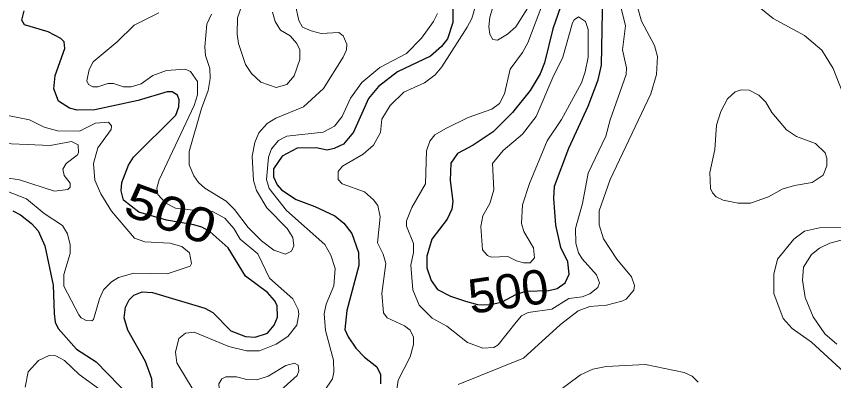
# Model space of a CAD drawing. Extents: x 577 to 602.9, y 7483.8 to 7511.6.
# Drawn here: x 579.985 to 581.887, y 7499.874 to 7500.722 of the extents above; entities that cross this region are included whole.
import ezdxf
from ezdxf.enums import TextEntityAlignment as Align

# ---------------------------------------------------------------- set-up
doc = ezdxf.new("R2010")
doc.units = 0
doc.header["$LTSCALE"] = 0.032
doc.layers.add('1', color=7, linetype='Continuous', lineweight=25)
doc.layers.add('2', color=7, linetype='Continuous', lineweight=13)
doc.layers.add('61', color=7, linetype='Continuous')

msp = doc.modelspace()

# ---------------------------------------------------------------- linework, layer by layer
at = {"layer": '1'}
for points in [[(581.0008, 7500.7727), (581.0008, 7500.7075), (580.9881, 7500.6701), (580.9745, 7500.6518), (580.9483, 7500.6296), (580.872, 7500.593), (580.8274, 7500.5588), (580.8044, 7500.531), (580.7694, 7500.4522), (580.7463, 7500.4244), (580.7241, 7500.4141), (580.7082, 7500.4109), (580.6827, 7500.4157), (580.6382, 7500.4149), (580.6032, 7500.3966), (580.5829, 7500.3672), (580.5829, 7500.3484), (580.5913, 7500.3298), (580.6016, 7500.3178), (580.6358, 7500.2956), (580.6795, 7500.2797), (580.7257, 7500.2574), (580.7471, 7500.2407), (580.7654, 7500.2161), (580.7813, 7500.1723), (580.7821, 7500.1421), (580.7535, 7500.0371)], [(581.2568, 7500.7608), (581.233, 7500.6932), (581.2139, 7500.6136), (581.2036, 7500.5882), (581.1805, 7500.5492), (581.1391, 7500.4983), (581.0946, 7500.453), (581.0477, 7500.422), (581.0111, 7500.4029), (580.996, 7500.3799), (580.9944, 7500.3401), (581.0008, 7500.2908), (580.9984, 7500.2733), (580.9873, 7500.2495), (580.9515, 7500.2033), (580.9404, 7500.1636), (580.9404, 7500.1365), (580.9499, 7500.1071), (580.965, 7500.0864), (580.9952, 7500.0705), (581.0298, 7500.0587), (581.0579, 7500.0508), (581.087, 7500.0502), (581.1154, 7500.057), (581.1469, 7500.0742), (581.1702, 7500.0823), (581.2242, 7500.0833), (581.2433, 7500.088), (581.2624, 7500.1016), (581.2711, 7500.1214), (581.268, 7500.1501), (581.2521, 7500.1835), (581.2401, 7500.2359), (581.2354, 7500.298), (581.237, 7500.3266), (581.2704, 7500.4149), (581.3157, 7500.5127), (581.3387, 7500.5747), (581.3467, 7500.6081), (581.3499, 7500.7743)], [(580.3018, 7500.0793), (580.4235, 7500.0427), (580.4418, 7500.0324), (580.4839, 7499.9894), (580.5181, 7499.9767), (580.5404, 7499.9751), (580.569, 7499.9847), (580.5849, 7500.003), (580.5921, 7500.0212), (580.5913, 7500.0491), (580.5857, 7500.0602), (580.569, 7500.0793), (580.5181, 7500.1167), (580.4776, 7500.1827), (580.4354, 7500.22), (580.4163, 7500.2312), (580.398, 7500.2367), (580.3341, 7500.2477), (580.2699, 7500.2658), (580.2342, 7500.294), (580.2287, 7500.3155), (580.2303, 7500.3353), (580.2454, 7500.3759), (580.2573, 7500.3942), (580.3559, 7500.492), (580.3631, 7500.5111), (580.3639, 7500.5278), (580.3599, 7500.5389), (580.3472, 7500.5461), (580.336, 7500.5461), (580.2684, 7500.5262), (580.1674, 7500.5047), (580.1261, 7500.5039), (580.1086, 7500.5087), (580.0824, 7500.5246), (580.072, 7500.5532), (580.0752, 7500.5842), (580.0975, 7500.647), (580.0959, 7500.6629), (580.0879, 7500.6709), (580.0585, 7500.686), (580.0036, 7500.7027), (579.9973, 7500.713), (580.0028, 7500.7353)], [(579.9766, 7500.2693), (579.9941, 7500.2598), (580.0195, 7500.2399), (580.0354, 7500.2224), (580.0506, 7500.1874), (580.0704, 7500.096), (580.0728, 7500.03), (580.0752, 7500.0101), (580.0816, 7499.995), (580.1245, 7499.9473), (580.1706, 7499.9179), (580.2509, 7499.8344)], [(580.3026, 7499.8399), (580.3002, 7499.8781), (580.2851, 7499.9187), (580.2438, 7499.991), (580.2358, 7500.0197), (580.239, 7500.0451), (580.247, 7500.0618), (580.2581, 7500.0729), (580.2772, 7500.0809), (580.3018, 7500.0793)], [(580.7535, 7500.0371), (580.7495, 7499.9926), (580.7567, 7499.9759), (580.775, 7499.9497), (580.7948, 7499.9282), (580.8235, 7499.9059), (580.8322, 7499.8884), (580.8322, 7499.8662)]]:
    msp.add_lwpolyline(points, dxfattribs=at)
at = {"layer": '2'}
for points in [[(581.3753, 7500.8101), (581.4024, 7500.7003), (581.3952, 7500.6439), (581.4047, 7500.6025), (581.4039, 7500.5866), (581.3666, 7500.4809), (581.357, 7500.4435), (581.3157, 7500.3568), (581.3022, 7500.286), (581.2863, 7500.228), (581.2871, 7500.1938), (581.2934, 7500.1715), (581.3014, 7500.1572), (581.3348, 7500.1198), (581.3419, 7500.1016), (581.3379, 7500.0904), (581.3197, 7500.0761), (581.3014, 7500.069), (581.2704, 7500.065), (581.2314, 7500.0403), (581.1757, 7500.0324), (581.1606, 7500.0244), (581.1479, 7500.0101), (581.1058, 7499.9568), (581.0962, 7499.9513), (581.0708, 7499.9497), (581.035, 7499.9624), (580.9865, 7500.0006), (580.9523, 7500.0189), (580.9221, 7500.0499), (580.9078, 7500.0849), (580.903, 7500.1429), (580.9093, 7500.1723), (580.9093, 7500.193), (580.8926, 7500.2336), (580.8926, 7500.2463), (580.9054, 7500.2773), (580.9372, 7500.3322), (580.9396, 7500.4093), (580.9467, 7500.4316), (580.9586, 7500.4459), (580.9841, 7500.461), (581.0366, 7500.4864), (581.0914, 7500.5063), (581.1089, 7500.519), (581.1209, 7500.5421), (581.1344, 7500.5993), (581.163, 7500.6383), (581.1749, 7500.6606), (581.2115, 7500.7568)], [(581.0127, 7499.8646), (581.1654, 7499.9258), (581.2513, 7500.0045), (581.2926, 7500.0364), (581.3197, 7500.0467), (581.3586, 7500.0499), (581.3936, 7500.0586), (581.4039, 7500.0634), (581.4222, 7500.0841), (581.4238, 7500.0952), (581.4167, 7500.1159), (581.3825, 7500.1564), (581.3515, 7500.2041), (581.3411, 7500.2367), (581.3411, 7500.2693), (581.3666, 7500.3425), (581.4612, 7500.5421), (581.4747, 7500.5866), (581.4771, 7500.6288), (581.4699, 7500.6542), (581.4397, 7500.7107), (581.4143, 7500.8029)], [(580.5809, 7500.7321), (580.5873, 7500.7099), (580.5992, 7500.69), (580.6223, 7500.6765), (580.6374, 7500.659), (580.6445, 7500.6439), (580.6445, 7500.6216), (580.631, 7500.5834), (580.6143, 7500.5636), (580.5897, 7500.5564), (580.5539, 7500.5691), (580.5316, 7500.589), (580.5181, 7500.6097), (580.5014, 7500.659), (580.4982, 7500.6804), (580.499, 7500.7186), (580.5237, 7500.7878)], [(581.1789, 7500.748), (581.1471, 7500.6979), (581.128, 7500.6804), (581.1042, 7500.6669), (581.0938, 7500.6685), (581.0867, 7500.6804), (581.0843, 7500.6979), (581.0867, 7500.7202), (581.0994, 7500.7616)], [(580.4386, 7500.7274), (580.4283, 7500.7043), (580.4235, 7500.651), (580.4251, 7500.6311), (580.4346, 7500.6009), (580.4354, 7500.5771), (580.4314, 7500.5492), (580.4155, 7500.5079), (580.3869, 7500.4077), (580.3869, 7500.3767), (580.398, 7500.3504), (580.4084, 7500.3353), (580.4235, 7500.3218), (580.4728, 7500.2916), (580.4927, 7500.2725), (580.5245, 7500.2304), (580.5555, 7500.1994), (580.5841, 7500.1779), (580.6112, 7500.1684), (580.6247, 7500.1755), (580.6302, 7500.1874), (580.6278, 7500.2073), (580.6151, 7500.228), (580.5674, 7500.2765), (580.5436, 7500.3163), (580.5364, 7500.3401), (580.5332, 7500.3966), (580.5396, 7500.4284), (580.5491, 7500.4506), (580.5682, 7500.4729), (580.5889, 7500.4848), (580.6533, 7500.5111), (580.6994, 7500.554), (580.7455, 7500.6272), (580.7527, 7500.6439), (580.7535, 7500.6574), (580.7455, 7500.6765), (580.7352, 7500.6844), (580.6938, 7500.682), (580.6708, 7500.6884), (580.6509, 7500.6971), (580.6422, 7500.7123), (580.6334, 7500.7512)], [(581.0541, 7500.7488), (581.0445, 7500.717), (581.0342, 7500.6971), (580.9753, 7500.6049), (580.9594, 7500.5858), (580.9348, 7500.5675), (580.8863, 7500.5453), (580.8545, 7500.5143), (580.8354, 7500.4824), (580.8322, 7500.4514), (580.8163, 7500.422), (580.7917, 7500.4013), (580.7439, 7500.3735), (580.7336, 7500.3608), (580.7336, 7500.3425), (580.7431, 7500.3322), (580.7948, 7500.3131), (580.8163, 7500.2948), (580.8258, 7500.2813), (580.8314, 7500.255), (580.8251, 7500.1946), (580.8386, 7500.1684), (580.8449, 7500.1469), (580.8354, 7500.0769), (580.8394, 7500.0316), (580.8481, 7500.0197), (580.8879, 7500.0014), (580.9014, 7499.991), (580.9093, 7499.9751), (580.9093, 7499.9576), (580.9014, 7499.929), (580.8736, 7499.8749), (580.8688, 7499.8431)], [(581.7172, 7500.7401), (581.7459, 7500.717), (581.819, 7500.6773), (581.8596, 7500.6431), (581.8858, 7500.6009), (581.9224, 7500.5079)], [(580.2589, 7500.7019), (580.3161, 7500.7305)], [(580.965, 7500.7289), (580.9555, 7500.7099), (580.9276, 7500.6717), (580.8926, 7500.6359), (580.8306, 7500.6033), (580.7885, 7500.5683), (580.7622, 7500.5317), (580.7431, 7500.4888), (580.7249, 7500.4665), (580.6986, 7500.4522), (580.6143, 7500.4435), (580.5945, 7500.4331), (580.5785, 7500.4133), (580.5714, 7500.3942), (580.5666, 7500.3425), (580.573, 7500.321), (580.6135, 7500.2701), (580.7026, 7500.1906), (580.7169, 7500.166), (580.7265, 7500.135), (580.7233, 7500.0944), (580.7058, 7500.0515), (580.701, 7500.0292), (580.7042, 7499.9902), (580.7225, 7499.9211), (580.7233, 7499.8932), (580.7201, 7499.8781), (580.701, 7499.8495)], [(580.3965, 7499.8527), (580.3583, 7499.9155), (580.3551, 7499.9401), (580.3631, 7499.9719), (580.3782, 7499.9847), (580.3988, 7499.9863), (580.4792, 7499.9529), (580.5205, 7499.9433), (580.5507, 7499.9433), (580.5897, 7499.9584), (580.6167, 7499.9767), (580.6374, 7500.003), (580.6422, 7500.0284), (580.6406, 7500.0395), (580.6278, 7500.0642), (580.5738, 7500.1127), (580.5467, 7500.1691), (580.5054, 7500.2033), (580.4911, 7500.228), (580.4696, 7500.2518), (580.441, 7500.2677), (580.4275, 7500.2709), (580.402, 7500.2701), (580.3551, 7500.2758), (580.3322, 7500.2867), (580.3136, 7500.3075), (580.3115, 7500.3217), (580.3169, 7500.3413), (580.3988, 7500.5143), (580.406, 7500.5397), (580.406, 7500.5707), (580.3901, 7500.5938), (580.3774, 7500.5993), (580.3344, 7500.5962), (580.3026, 7500.5842), (580.2748, 7500.5651), (580.2517, 7500.558), (580.2342, 7500.558), (580.2104, 7500.5659), (580.1977, 7500.5659), (580.1746, 7500.558), (580.1627, 7500.558), (580.1523, 7500.5636), (580.1484, 7500.5723), (580.1539, 7500.5985), (580.1635, 7500.616), (580.2191, 7500.6629), (580.2589, 7500.7019)], [(579.9623, 7500.3147), (580.0084, 7500.2972), (580.049, 7500.263), (580.0919, 7500.2351), (580.1038, 7500.2153), (580.1102, 7500.1898), (580.1102, 7500.1699), (580.0951, 7500.1206), (580.0951, 7500.0936), (580.1301, 7500.0268), (580.1356, 7500.0197), (580.1468, 7500.0141), (580.1603, 7500.0133), (580.1643, 7500.0165), (580.1778, 7500.0642), (580.1873, 7500.0849), (580.2064, 7500.1039), (580.2223, 7500.1143), (580.2581, 7500.1238), (580.336, 7500.1222), (580.3893, 7500.1405), (580.3925, 7500.1469), (580.3877, 7500.1715), (580.3694, 7500.1858), (580.3416, 7500.1938), (580.2835, 7500.197), (580.2597, 7500.2057), (580.2064, 7500.2685), (580.181, 7500.3091), (580.1674, 7500.3409), (580.1643, 7500.3791), (580.1746, 7500.4157), (580.2056, 7500.4586), (580.2064, 7500.4673), (580.1992, 7500.4761), (580.169, 7500.4737), (580.1317, 7500.4546), (580.08, 7500.4554), (580.049, 7500.4642), (580.0148, 7500.4809), (579.9448, 7500.4952)], [(579.9186, 7500.4276), (580.0633, 7500.4212), (580.1126, 7500.4308), (580.1285, 7500.4228), (580.1293, 7500.4045), (580.1261, 7500.399), (580.1006, 7500.3791), (580.0927, 7500.3663), (580.0959, 7500.3512), (580.1102, 7500.3337), (580.1102, 7500.3242), (580.1046, 7500.3186), (580.0736, 7500.3147), (579.9917, 7500.3417), (579.9567, 7500.3465)], [(581.9168, 7500.2312), (581.854, 7500.2296), (581.819, 7500.2216), (581.7944, 7500.2033), (581.7562, 7500.1564), (581.7475, 7500.1214), (581.7475, 7500.0769), (581.7697, 7500.0181), (581.7904, 7499.995), (581.8357, 7499.9632), (581.9311, 7499.8757)], [(581.8946, 7499.9584), (581.8667, 7499.9831), (581.8397, 7500.022), (581.8206, 7500.0674), (581.8143, 7500.1079), (581.8166, 7500.1381), (581.8357, 7500.1676), (581.854, 7500.1819), (581.8779, 7500.1938), (581.9049, 7500.201)], [(580.0052, 7499.8582), (580.0124, 7499.894), (580.0362, 7499.9203), (580.0609, 7499.9322), (580.0768, 7499.9314), (580.0967, 7499.9203), (580.1309, 7499.8877), (580.1841, 7499.8495)], [(581.5717, 7499.8702), (581.5574, 7499.8845), (581.5391, 7499.8924), (581.4493, 7499.9115), (581.3578, 7499.9067), (581.3268, 7499.9004), (581.2974, 7499.8869), (581.2338, 7499.8399)]]:
    msp.add_lwpolyline(points, dxfattribs=at)
for points in [[(581.066, 7500.2328), (581.07, 7500.1787), (581.0811, 7500.1652), (581.0898, 7500.1612), (581.1288, 7500.1628), (581.1487, 7500.1524), (581.1654, 7500.1485), (581.1805, 7500.1485), (581.1908, 7500.1596), (581.1884, 7500.1827), (581.1662, 7500.2208), (581.1606, 7500.2399), (581.163, 7500.2829), (581.1789, 7500.333), (581.2203, 7500.4323), (581.2537, 7500.4816), (581.2998, 7500.5675), (581.3085, 7500.593), (581.3157, 7500.6272), (581.3157, 7500.6916), (581.3093, 7500.7099), (581.2934, 7500.721), (581.2831, 7500.7138), (581.2791, 7500.7067), (581.2568, 7500.6272), (581.233, 7500.5795), (581.1948, 7500.4888), (581.163, 7500.4475), (581.1177, 7500.4101), (581.093, 7500.3791), (581.0962, 7500.3178), (581.0867, 7500.286), (581.0708, 7500.2574)], [(581.796, 7500.3282), (581.8373, 7500.3353), (581.8628, 7500.352), (581.8715, 7500.3743), (581.8715, 7500.3918), (581.8675, 7500.4045), (581.8445, 7500.426), (581.8007, 7500.4427), (581.7769, 7500.4578), (581.7435, 7500.4983), (581.7292, 7500.5222), (581.7125, 7500.5389), (581.6902, 7500.55), (581.6719, 7500.5508), (581.6576, 7500.5461), (581.6401, 7500.5302), (581.6242, 7500.5007), (581.6147, 7500.4689), (581.6107, 7500.4117), (581.5988, 7500.3584), (581.6003, 7500.321), (581.6051, 7500.3115), (581.6139, 7500.3019), (581.6298, 7500.294), (581.6648, 7500.2868), (581.6934, 7500.2868), (581.7355, 7500.3019), (581.7673, 7500.3194)], [(580.4672, 7499.7286), (580.4799, 7499.7199), (580.4927, 7499.7167), (580.5038, 7499.7199), (580.5118, 7499.727), (580.5372, 7499.7811), (580.5626, 7499.8185), (580.6382, 7499.8861), (580.6422, 7499.8964), (580.6406, 7499.9099), (580.6318, 7499.9147), (580.6119, 7499.9091), (580.5706, 7499.8845), (580.5444, 7499.8757), (580.5213, 7499.8765), (580.4974, 7499.8829), (580.472, 7499.8829), (580.4625, 7499.8781), (580.4561, 7499.8662), (580.4569, 7499.8551), (580.4823, 7499.8058), (580.4823, 7499.7867), (580.4688, 7499.7676), (580.4617, 7499.7501)]]:
    msp.add_lwpolyline(points, close=True, dxfattribs=at)

# ---------------------------------------------------------------- texts
at = {"layer": '61'}
for rotation, width, p in [(339.781, 1.2, (580.3302, 7500.2249)), (8.322, 1.05, (581.1353, 7500.0424))]:
    msp.add_text('500', height=0.08, rotation=rotation, dxfattribs=dict(at, width=width)).set_placement(p, align=Align.CENTER)

doc.saveas('drawing.dxf')
